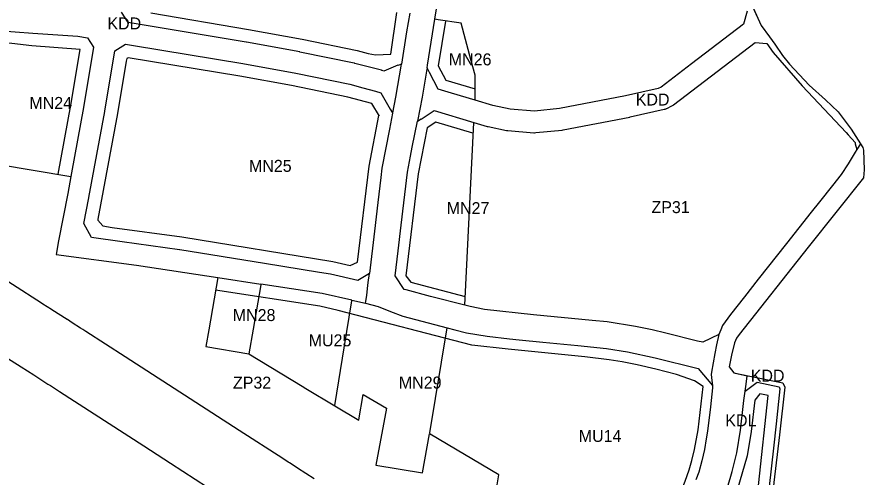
# Model space of a CAD drawing. Extents: x 7428103 to 7431580, y 5545880 to 5549002.
# Drawn here: x 7430729.6 to 7431122.6, y 5547228.4 to 5547441.7 of the extents above; entities that cross this region are included whole.
import ezdxf

# ---------------------------------------------------------------- set-up
doc = ezdxf.new("R2010")
doc.units = 0
for name, color, linetype in [('CZ_L_granica obszaru objętego planem', 7, 'Continuous'), ('CZ_L_linie rozgraniczające tereny o różnym przeznaczeniu oraz różnych warunkach ich zabudowy i zagospodarowania', 7, 'Continuous'), ('CZ_L_maksymalne nieprzekraczalne linie zabudowy', 7, 'Continuous'), ('CZ_L_opisy_linie rozgraniczające tereny o różnym przeznaczeniu oraz różnych warunkach ich zabudowy i zagospodarowania', 7, 'Continuous')]:
    doc.layers.add(name, color=color, linetype=linetype)

msp = doc.modelspace()

# ---------------------------------------------------------------- linework, layer by layer
at = {"layer": 'CZ_L_granica obszaru objętego planem'}
for p, q in [((7431066, 5547457.29), (7431074.9, 5547437.84)), ((7431074.9, 5547437.84), (7431078.67, 5547432.53)), ((7431078.67, 5547432.53), (7431081.21, 5547429.06)), ((7431081.21, 5547429.06), (7431084.68, 5547423.88)), ((7431084.68, 5547423.88), (7431087.93, 5547419.9)), ((7431087.93, 5547419.9), (7431097.2, 5547410.15)), ((7431097.2, 5547410.15), (7431104.64, 5547403.36)), ((7431104.64, 5547403.36), (7431110.55, 5547397.75)), ((7431110.55, 5547397.75), (7431116.54, 5547389.77)), ((7431116.54, 5547389.77), (7431121.98, 5547381.16)), ((7431121.98, 5547381.16), (7431122.33, 5547379.93)), ((7431122.33, 5547379.93), (7431122.59, 5547370.83)), ((7431122.59, 5547370.83), (7431122.26, 5547367.17)), ((7431122.26, 5547367.17), (7431096.66, 5547334.93)), ((7431096.66, 5547334.93), (7431064.69, 5547294.55)), ((7431063.46, 5547292.76), (7431062.41, 5547290.61)), ((7431064.69, 5547294.55), (7431063.46, 5547292.76)), ((7431062.41, 5547290.61), (7431061.1, 5547285)), ((7431061.1, 5547285), (7431060.06, 5547279.46)), ((7431060.06, 5547279.46), (7431062.23, 5547276.79)), ((7431062.23, 5547276.79), (7431069.54, 5547275.12)), ((7431069.54, 5547275.12), (7431084.96, 5547272.05)), ((7431084.96, 5547272.05), (7431085.82, 5547270.13)), ((7431085.82, 5547270.13), (7431083.35, 5547248.03)), ((7431083.35, 5547248.03), (7431080.69, 5547225.95))]:
    msp.add_line(p, q, dxfattribs=at)
at = {"layer": 'CZ_L_linie rozgraniczające tereny o różnym przeznaczeniu oraz różnych warunkach ich zabudowy i zagospodarowania'}
for p, q in [((7430923.49, 5547440.65), (7430924.59, 5547447.41)), ((7431068.4, 5547444.49), (7431066.66, 5547438.33)), ((7430781.17, 5547439.11), (7430778.02, 5547444.03)), ((7430911.79, 5547443.46), (7430910.38, 5547434.78)), ((7430920.03, 5547419.41), (7430923.49, 5547440.65)), ((7430924.97, 5547440.42), (7430923.49, 5547440.65)), ((7430924.97, 5547440.41), (7430924.97, 5547440.42)), ((7430935.73, 5547438.8), (7430924.97, 5547440.41)), ((7430836, 5547430.01), (7430781.17, 5547439.11)), ((7430940.35, 5547421.45), (7430935.73, 5547438.8)), ((7431066.66, 5547438.33), (7431042.5, 5547419.99)), ((7430710.81, 5547436.18), (7430736.98, 5547434.26)), ((7430736.98, 5547434.26), (7430757.87, 5547432.78)), ((7430757.87, 5547432.78), (7430757.89, 5547432.83)), ((7430757.89, 5547432.83), (7430762.29, 5547432.11)), ((7430910.38, 5547434.78), (7430907.96, 5547419.92)), ((7430762.29, 5547432.11), (7430765.15, 5547427.67)), ((7430775.03, 5547426.09), (7430779.88, 5547429.19)), ((7430779.88, 5547429.19), (7430783.72, 5547428.55)), ((7430783.72, 5547428.55), (7430834.32, 5547420.15)), ((7430836.08, 5547430), (7430836, 5547430.01)), ((7430860.75, 5547425.5), (7430836.08, 5547430)), ((7431048.55, 5547412.03), (7431072.07, 5547429.89)), ((7431072.07, 5547429.89), (7431077.54, 5547429.44)), ((7431077.54, 5547429.44), (7431080.47, 5547425.23)), ((7430765.15, 5547427.67), (7430760.49, 5547399.74)), ((7430770.35, 5547398.06), (7430775.03, 5547426.09)), ((7430860.87, 5547425.48), (7430860.75, 5547425.5)), ((7430886.1, 5547420.28), (7430860.87, 5547425.48)), ((7431080.47, 5547425.23), (7431093.8, 5547409.88)), ((7430942.1, 5547414.79), (7430940.35, 5547421.45)), ((7430834.32, 5547420.15), (7430858.91, 5547415.68)), ((7430886.19, 5547420.26), (7430886.1, 5547420.28)), ((7430886.35, 5547420.22), (7430886.19, 5547420.26)), ((7430898.66, 5547417.02), (7430886.35, 5547420.22)), ((7430898.81, 5547416.97), (7430898.66, 5547417.02)), ((7430899, 5547416.92), (7430898.81, 5547416.97)), ((7430899.87, 5547416.62), (7430899, 5547416.92)), ((7430906.36, 5547419.43), (7430899.87, 5547416.62)), ((7430905.35, 5547404.6), (7430907.96, 5547419.92)), ((7430907.96, 5547419.92), (7430906.34, 5547419.3)), ((7430906.34, 5547419.3), (7430906.36, 5547419.43)), ((7430919.84, 5547418.23), (7430919.58, 5547416.59)), ((7430919.84, 5547418.23), (7430920.03, 5547419.41)), ((7430921, 5547416), (7430919.84, 5547418.23)), ((7431042.48, 5547419.97), (7431028.49, 5547409.23)), ((7431042.5, 5547419.99), (7431042.48, 5547419.97)), ((7430858.91, 5547415.68), (7430883.95, 5547410.52)), ((7430919.58, 5547416.59), (7430917.59, 5547404.62)), ((7430925.02, 5547408.23), (7430921, 5547416.01)), ((7430921, 5547416.01), (7430921, 5547416)), ((7430942.16, 5547404.66), (7430942.1, 5547414.79)), ((7430883.95, 5547410.52), (7430890.06, 5547408.92)), ((7430890.06, 5547408.92), (7430895.97, 5547407.39)), ((7431028.49, 5547409.23), (7431027.13, 5547408.56)), ((7431034.19, 5547401), (7431048.55, 5547412.03)), ((7431093.8, 5547409.88), (7431093.92, 5547409.76)), ((7431093.92, 5547409.76), (7431093.93, 5547409.75)), ((7431093.93, 5547409.75), (7431114.3, 5547388.17)), ((7430895.97, 5547407.39), (7430898.35, 5547406.58)), ((7430898.35, 5547406.58), (7430902.73, 5547399.06)), ((7430931.16, 5547406.4), (7430925.02, 5547408.23)), ((7430942.09, 5547403.14), (7430931.16, 5547406.4)), ((7431011.91, 5547405.15), (7430981.34, 5547399.25)), ((7431027.13, 5547408.56), (7431011.91, 5547405.15)), ((7430903.92, 5547397.35), (7430905.35, 5547404.6)), ((7430917.59, 5547404.62), (7430915.36, 5547393.37)), ((7430942.09, 5547403.14), (7430942.16, 5547404.66)), ((7430950.39, 5547400.66), (7430942.09, 5547403.14)), ((7430760.49, 5547399.74), (7430754.89, 5547369.47)), ((7430762.95, 5547358.09), (7430770.33, 5547397.97)), ((7430770.33, 5547397.97), (7430770.35, 5547398.06)), ((7430902.73, 5547399.06), (7430902.73, 5547399.05)), ((7430902.73, 5547399.05), (7430903.76, 5547397.26)), ((7430903.76, 5547397.26), (7430903.92, 5547397.35)), ((7430903.76, 5547397.26), (7430903.87, 5547397.09)), ((7430917.1, 5547394.41), (7430923.2, 5547398.34)), ((7430923.2, 5547398.34), (7430941.58, 5547392.86)), ((7430958.42, 5547399), (7430950.39, 5547400.66)), ((7430969.75, 5547398.09), (7430958.42, 5547399)), ((7430981.34, 5547399.25), (7430969.75, 5547398.09)), ((7431014.03, 5547395.37), (7431029.9, 5547398.93)), ((7431029.9, 5547398.93), (7431030.3, 5547399.04)), ((7431030.3, 5547399.04), (7431030.61, 5547399.14)), ((7431030.61, 5547399.14), (7431030.91, 5547399.27)), ((7431030.91, 5547399.27), (7431031.02, 5547399.33)), ((7431031.02, 5547399.33), (7431033.36, 5547400.48)), ((7431033.36, 5547400.48), (7431033.99, 5547400.86)), ((7431033.99, 5547400.86), (7431034.09, 5547400.92)), ((7431034.09, 5547400.92), (7431034.15, 5547400.96)), ((7431034.15, 5547400.96), (7431034.19, 5547401)), ((7430903.87, 5547397.09), (7430902.4, 5547389.68)), ((7430912.98, 5547381.37), (7430915.36, 5547393.37)), ((7430915.36, 5547393.37), (7430917.11, 5547394.46)), ((7430917.11, 5547394.46), (7430917.1, 5547394.41)), ((7430983.01, 5547389.39), (7431013.88, 5547395.34)), ((7431013.88, 5547395.34), (7431014.03, 5547395.37)), ((7430902.4, 5547389.68), (7430898.87, 5547371.65)), ((7430937.37, 5547308.07), (7430941.58, 5547392.86)), ((7430941.58, 5547392.86), (7430947.74, 5547391.02)), ((7430947.74, 5547391.02), (7430947.75, 5547391.02)), ((7430947.75, 5547391.02), (7430948.07, 5547390.93)), ((7430948.07, 5547390.93), (7430948.15, 5547390.92)), ((7430948.15, 5547390.92), (7430956.7, 5547389.14)), ((7430970.3, 5547388.1), (7430982.56, 5547389.32)), ((7430982.56, 5547389.32), (7430983.01, 5547389.39)), ((7430956.7, 5547389.14), (7430957.31, 5547389.06)), ((7430957.31, 5547389.06), (7430969.4, 5547388.09)), ((7430969.4, 5547388.09), (7430969.68, 5547388.08)), ((7430969.68, 5547388.08), (7430970.3, 5547388.1)), ((7431114.3, 5547388.17), (7431115.24, 5547387.04)), ((7431115.24, 5547387.04), (7431118.39, 5547383.61)), ((7430912.15, 5547377.15), (7430912.98, 5547381.37)), ((7431118.39, 5547383.61), (7431118.48, 5547383.05)), ((7431118.48, 5547383.05), (7431118.51, 5547382.99)), ((7431118.51, 5547382.99), (7431118.51, 5547382.97)), ((7431118.51, 5547382.97), (7431119.24, 5547380.27)), ((7431120.88, 5547382.89), (7431119.24, 5547380.27)), ((7430695.95, 5547377.64), (7430754.58, 5547367.81)), ((7431118.48, 5547379.05), (7431115.17, 5547373.66)), ((7431119.24, 5547380.27), (7431118.48, 5547379.05)), ((7430910.73, 5547369.79), (7430912.15, 5547377.15)), ((7431115.17, 5547373.66), (7431112, 5547368.74)), ((7430898.87, 5547371.65), (7430898.35, 5547367.26)), ((7430907.81, 5547345.2), (7430910.73, 5547369.79)), ((7430754.58, 5547367.81), (7430753.12, 5547359.93)), ((7430754.89, 5547369.47), (7430754.58, 5547367.81)), ((7430898.35, 5547367.26), (7430896.97, 5547355.64)), ((7431112, 5547368.74), (7431107.92, 5547363.61)), ((7431107.92, 5547363.61), (7431101.87, 5547355.98)), ((7430753.12, 5547359.93), (7430748.93, 5547338.01)), ((7430760.56, 5547346.04), (7430762.9, 5547357.85)), ((7430762.9, 5547357.85), (7430762.91, 5547357.9)), ((7430762.91, 5547357.9), (7430762.95, 5547358.09)), ((7430896.97, 5547355.64), (7430895.39, 5547342.38)), ((7431101.87, 5547355.98), (7431098.13, 5547351.27)), ((7431098.13, 5547351.27), (7431086.59, 5547336.73)), ((7430764.19, 5547339.42), (7430760.56, 5547346.04)), ((7430895.39, 5547342.38), (7430893.07, 5547322.83)), ((7430906.4, 5547333.31), (7430907.81, 5547345.2)), ((7430778.4, 5547337.5), (7430764.19, 5547339.42)), ((7430748.93, 5547338.01), (7430747.83, 5547331.55)), ((7430805.07, 5547333.81), (7430778.4, 5547337.5)), ((7431086.59, 5547336.73), (7431073.52, 5547320.2)), ((7430747.83, 5547331.55), (7430785.06, 5547326.68)), ((7430805.13, 5547333.8), (7430805.07, 5547333.81)), ((7430805.19, 5547333.79), (7430805.13, 5547333.8)), ((7430844.47, 5547327.43), (7430805.19, 5547333.79)), ((7430905.03, 5547321.77), (7430906.4, 5547333.31)), ((7430738.77, 5547310.44), (7430711.71, 5547327.7)), ((7430785.06, 5547326.68), (7430822.71, 5547320.93)), ((7430869.92, 5547323.31), (7430844.47, 5547327.43)), ((7430875, 5547322.51), (7430869.92, 5547323.31)), ((7430887.67, 5547319.62), (7430875, 5547322.51)), ((7430893.07, 5547322.83), (7430887.67, 5547319.62)), ((7430892.58, 5547318.67), (7430893.07, 5547322.83)), ((7430822.71, 5547320.93), (7430818.59, 5547296.71)), ((7430822.71, 5547320.93), (7430842.79, 5547317.86)), ((7430892.24, 5547315.85), (7430892.58, 5547318.67)), ((7430909.3, 5547315.44), (7430905.03, 5547321.77)), ((7431073.52, 5547320.2), (7431067.09, 5547312.01)), ((7430842.74, 5547317.58), (7430839.1, 5547296.93)), ((7430842.76, 5547317.72), (7430842.74, 5547317.58)), ((7430842.79, 5547317.86), (7430842.76, 5547317.72)), ((7430871.14, 5547313.54), (7430842.79, 5547317.86)), ((7430891.85, 5547312.53), (7430892.24, 5547315.85)), ((7430910.08, 5547315.29), (7430909.3, 5547315.44)), ((7430921.52, 5547312.17), (7430910.08, 5547315.29)), ((7430884.97, 5547310.49), (7430871.14, 5547313.54)), ((7430891.29, 5547309.1), (7430891.85, 5547312.53)), ((7430937.37, 5547308.07), (7430921.52, 5547312.17)), ((7431067.09, 5547312.01), (7431060.57, 5547303.73)), ((7430741.38, 5547308.77), (7430738.77, 5547310.44)), ((7430741.65, 5547308.6), (7430741.38, 5547308.77)), ((7430745.68, 5547306.03), (7430741.65, 5547308.6)), ((7430881.41, 5547288.4), (7430884.92, 5547310.16)), ((7430884.92, 5547310.16), (7430884.96, 5547310.37)), ((7430884.96, 5547310.37), (7430884.97, 5547310.49)), ((7430884.97, 5547310.49), (7430891.29, 5547309.1)), ((7430891.29, 5547309.1), (7430897.15, 5547307.44)), ((7430897.15, 5547307.44), (7430897.16, 5547307.43)), ((7430897.16, 5547307.43), (7430902.87, 5547305.24)), ((7430939.86, 5547307.43), (7430937.37, 5547308.07)), ((7430946.45, 5547306.07), (7430939.86, 5547307.43)), ((7430745.7, 5547306.02), (7430745.68, 5547306.03)), ((7430745.7, 5547306.01), (7430745.7, 5547306.02)), ((7430752.93, 5547301.4), (7430745.7, 5547306.01)), ((7430902.87, 5547305.24), (7430908.54, 5547303.06)), ((7430908.54, 5547303.06), (7430929.17, 5547297.61)), ((7430969.26, 5547303.67), (7430946.45, 5547306.07)), ((7430996.45, 5547301.05), (7430969.26, 5547303.67)), ((7431060.57, 5547303.73), (7431056.97, 5547298.69)), ((7430752.96, 5547301.39), (7430752.93, 5547301.4)), ((7430752.93, 5547301.4), (7430752.93, 5547301.4)), ((7430755.27, 5547299.91), (7430752.96, 5547301.39)), ((7430759.13, 5547297.45), (7430755.27, 5547299.91)), ((7431003.38, 5547300.31), (7430996.45, 5547301.05)), ((7431016.54, 5547298.2), (7431003.38, 5547300.31)), ((7430705.22, 5547296.26), (7430731.53, 5547279.48)), ((7430760.12, 5547296.82), (7430759.13, 5547297.45)), ((7430760.15, 5547296.79), (7430760.12, 5547296.82)), ((7430760.19, 5547296.78), (7430760.15, 5547296.79)), ((7430761.53, 5547295.91), (7430760.19, 5547296.78)), ((7430779.78, 5547284.14), (7430761.53, 5547295.91)), ((7430818.59, 5547296.71), (7430817.23, 5547289.01)), ((7430839.1, 5547296.93), (7430837.11, 5547285.61)), ((7430921.12, 5547248.95), (7430929.17, 5547297.61)), ((7430929.17, 5547297.61), (7430932.66, 5547296.69)), ((7430932.66, 5547296.69), (7430938.18, 5547295.26)), ((7430938.18, 5547295.26), (7430947.66, 5547293.67)), ((7431024.3, 5547296.73), (7431016.54, 5547298.2)), ((7431030.55, 5547295.13), (7431024.3, 5547296.73)), ((7431045.28, 5547291.37), (7431030.55, 5547295.13)), ((7431056.08, 5547296.69), (7431055.22, 5547294.57)), ((7431056.97, 5547298.69), (7431056.08, 5547296.69)), ((7430947.66, 5547293.67), (7430958.06, 5547292.51)), ((7430958.06, 5547292.51), (7430962.6, 5547292.06)), ((7430962.6, 5547292.06), (7430973.61, 5547290.98)), ((7430973.61, 5547290.98), (7430989.81, 5547289.43)), ((7431047.74, 5547290.9), (7431045.28, 5547291.37)), ((7431055.22, 5547294.57), (7431047.74, 5547290.9)), ((7431055.22, 5547294.57), (7431054.13, 5547289.69)), ((7430817.23, 5547289.01), (7430837.09, 5547285.52)), ((7430877.23, 5547262.5), (7430881.41, 5547288.4)), ((7430989.81, 5547289.43), (7431003.05, 5547288.01)), ((7431003.05, 5547288.01), (7431012.89, 5547286.45)), ((7431054.13, 5547289.69), (7431053.34, 5547285.72)), ((7430832.65, 5547250.02), (7430779.78, 5547284.14)), ((7430837.11, 5547285.61), (7430837.09, 5547285.52)), ((7430837.09, 5547285.52), (7430861.88, 5547270.51)), ((7431012.89, 5547286.45), (7431025.65, 5547283.76)), ((7431025.65, 5547283.76), (7431045.59, 5547278.69)), ((7431053.34, 5547285.72), (7431051.86, 5547276.97)), ((7430731.53, 5547279.48), (7430737.4, 5547275.73)), ((7430737.4, 5547275.73), (7430743.95, 5547271.55)), ((7431045.59, 5547278.69), (7431052.23, 5547270.87)), ((7431051.7, 5547275.97), (7431051.69, 5547275.92)), ((7431051.69, 5547275.92), (7431051.98, 5547273.15)), ((7431051.86, 5547276.97), (7431051.7, 5547275.97)), ((7431067.84, 5547271.42), (7431068.35, 5547275.39)), ((7430743.95, 5547271.55), (7430745.1, 5547270.81)), ((7431051.98, 5547273.15), (7431052.23, 5547270.87)), ((7431067.43, 5547268.21), (7431073.04, 5547272.38)), ((7431067.43, 5547268.21), (7431067.84, 5547271.42)), ((7431073.04, 5547272.38), (7431083.28, 5547270.23)), ((7430745.1, 5547270.81), (7430749.39, 5547268.04)), ((7430749.39, 5547268.04), (7430788.46, 5547242.83)), ((7430861.88, 5547270.51), (7430863.55, 5547269.51)), ((7430863.55, 5547269.51), (7430877.05, 5547261.42)), ((7431052.35, 5547269.73), (7431051.41, 5547261.01)), ((7431052.23, 5547270.87), (7431052.35, 5547269.73)), ((7431066.89, 5547263.95), (7431067.43, 5547268.21)), ((7431083.49, 5547269.39), (7431081.75, 5547253.03)), ((7431083.28, 5547270.23), (7431083.49, 5547269.39)), ((7430888.2, 5547254.88), (7430890.21, 5547266.7)), ((7430890.21, 5547266.7), (7430900.97, 5547260.33)), ((7431066.56, 5547261.16), (7431066.89, 5547263.95)), ((7430877.05, 5547261.42), (7430877.11, 5547261.79)), ((7430877.05, 5547261.42), (7430888.18, 5547254.75)), ((7430877.11, 5547261.79), (7430877.23, 5547262.5)), ((7430900.97, 5547260.33), (7430896.09, 5547233.89)), ((7431051.41, 5547261.01), (7431050.02, 5547249.63)), ((7431065.24, 5547250.19), (7431066.56, 5547261.16)), ((7430888.18, 5547254.75), (7430888.2, 5547254.88)), ((7431081.75, 5547253.03), (7431080.54, 5547241.86)), ((7430852.86, 5547236.98), (7430832.65, 5547250.02)), ((7430917.69, 5547230.4), (7430920.95, 5547248.51)), ((7430920.95, 5547248.51), (7430921.36, 5547248.27)), ((7430921.36, 5547248.27), (7430921.12, 5547248.95)), ((7430953.18, 5547229.45), (7430921.36, 5547248.27)), ((7431050.02, 5547249.63), (7431049.4, 5547246.08)), ((7431063.58, 5547239.61), (7431065.24, 5547250.19)), ((7431049.4, 5547246.08), (7431048.51, 5547241.12)), ((7430788.46, 5547242.83), (7430800.88, 5547234.82)), ((7431048.51, 5547241.12), (7431047.32, 5547235.9)), ((7431080.54, 5547241.86), (7431078.52, 5547223.98)), ((7430855.34, 5547235.38), (7430852.86, 5547236.98)), ((7431061.38, 5547230.91), (7431063.58, 5547239.61)), ((7430800.88, 5547234.82), (7430823.75, 5547220.06)), ((7430856.04, 5547234.93), (7430855.34, 5547235.38)), ((7430859.58, 5547232.64), (7430856.04, 5547234.93)), ((7430859.68, 5547232.57), (7430859.58, 5547232.64)), ((7430867.45, 5547227.54), (7430859.68, 5547232.57)), ((7430896.09, 5547233.89), (7430917.69, 5547230.4)), ((7431047.32, 5547235.9), (7431045.9, 5547230.71)), ((7430944.87, 5547178.9), (7430953.17, 5547229.4)), ((7430953.17, 5547229.4), (7430953.21, 5547229.43)), ((7430953.21, 5547229.43), (7430953.18, 5547229.45)), ((7431045.9, 5547230.71), (7431044.58, 5547227.18)), ((7431059.1, 5547223.16), (7431060.78, 5547228.77)), ((7431060.78, 5547228.77), (7431061.38, 5547230.91))]:
    msp.add_line(p, q, dxfattribs=at)
for points in [[(7430986.2, 5547553.19), (7430987.53, 5547551.64), (7431001.23, 5547536.94), (7431016.1, 5547524.03), (7431031.6, 5547511.12), (7431032.93, 5547512.33), (7431040.53, 5547506.15), (7431048.48, 5547494.34), (7431057.8, 5547475.24), (7431066, 5547457.29), (7431074.9, 5547437.84), (7431078.67, 5547432.53), (7431081.21, 5547429.06), (7431084.68, 5547423.88), (7431087.93, 5547419.9), (7431097.2, 5547410.15), (7431104.64, 5547403.36), (7431110.55, 5547397.75), (7431116.54, 5547389.77), (7431120.88, 5547382.89)], [(7431120.88, 5547382.89), (7431121.98, 5547381.16), (7431122.33, 5547379.93), (7431122.59, 5547370.83), (7431122.26, 5547367.17), (7431096.66, 5547334.93), (7431064.69, 5547294.55), (7431063.46, 5547292.76), (7431062.41, 5547290.61), (7431061.1, 5547285), (7431060.06, 5547279.46), (7431062.23, 5547276.79), (7431068.35, 5547275.39)], [(7431068.35, 5547275.39), (7431069.54, 5547275.12), (7431084.96, 5547272.05), (7431085.82, 5547270.13), (7431083.35, 5547248.03), (7431080.69, 5547225.95), (7431079.79, 5547215.06), (7431081.67, 5547180.91), (7431083.32, 5547166.12), (7431084.84, 5547159.41), (7431087.12, 5547146.98), (7431087.38, 5547145.53), (7431098.88, 5547102.12), (7431104.84, 5547079.92)]]:
    msp.add_lwpolyline(points, dxfattribs=at)
at = {"layer": 'CZ_L_maksymalne nieprzekraczalne linie zabudowy'}
for points in [[(7430791.64, 5547443.59), (7430837.04, 5547435.92), (7430861.91, 5547431.39), (7430887.38, 5547426.14), (7430892.46, 5547424.84), (7430895.93, 5547424.14), (7430903, 5547424.51), (7430905.78, 5547443.88)], [(7430928.43, 5547439.85), (7430925.04, 5547419.06), (7430928.49, 5547412.41), (7430942.14, 5547408.42)], [(7430748.68, 5547368.9), (7430754.58, 5547400.78), (7430758.84, 5547426.64), (7430736.55, 5547428.28), (7430705.89, 5547431.93)], [(7430897.74, 5547395.69), (7430894.29, 5547401.62), (7430883.03, 5547404.56), (7430856.97, 5547409.93), (7430833.01, 5547414.29), (7430781.12, 5547422.86), (7430780.54, 5547422.49), (7430780.3, 5547421.23), (7430776.24, 5547396.92), (7430767.05, 5547347.96), (7430767.15, 5547347.54), (7430769.46, 5547344.9), (7430773.79, 5547344.18), (7430806.01, 5547339.74), (7430876.13, 5547328.4), (7430884.19, 5547326.56), (7430887.62, 5547328.1), (7430892.94, 5547372.55), (7430897.54, 5547396.03)], [(7430941.12, 5547387.88), (7430923.95, 5547392.89), (7430919.85, 5547390.3), (7430915.67, 5547369.01), (7430910.05, 5547321.66), (7430912.34, 5547318.72), (7430937.57, 5547312.07)], [(7431017.73, 5547189.85), (7431027.03, 5547202.56), (7431031.87, 5547209.94), (7431036.83, 5547219.63), (7431039.6, 5547226.5), (7431041.43, 5547231.76), (7431042.67, 5547236.07), (7431043.87, 5547241.19), (7431045.56, 5547250.24), (7431047.92, 5547270.34), (7431043.85, 5547273.01), (7431035.58, 5547275.9), (7431025.98, 5547278.42), (7431017.33, 5547280.38), (7431010.34, 5547281.76), (7431004.39, 5547282.73), (7430993.11, 5547284.13), (7430957.52, 5547287.64), (7430940.59, 5547289.59), (7430878.65, 5547305.59), (7430870.04, 5547307.64), (7430821.75, 5547315.01)], [(7431073.56, 5547224.54), (7431078.12, 5547266.21), (7431074.22, 5547267.02), (7431071.96, 5547264.01), (7431070.21, 5547249.59), (7431068.38, 5547238.22), (7431062.7, 5547218.6)]]:
    msp.add_lwpolyline(points, dxfattribs=at)

# ---------------------------------------------------------------- texts
at = {"layer": 'CZ_L_opisy_linie rozgraniczające tereny o różnym przeznaczeniu oraz różnych warunkach ich zabudowy i zagospodarowania'}
for s, p in [('KDD', (7430771.55, 5547435.96)), ('MN26', (7430929.93, 5547419.3)), ('KDD', (7431016.67, 5547400.68)), ('MN24', (7430735.35, 5547399.1)), ('MN25', (7430837.23, 5547369.93)), ('MN27', (7430928.96, 5547350.32)), ('ZP31', (7431023.96, 5547350.79)), ('MN28', (7430829.71, 5547300.75)), ('MU25', (7430864.94, 5547289.03)), ('KDD', (7431070.02, 5547272.64)), ('ZP32', (7430829.8, 5547269.41)), ('MN29', (7430906.76, 5547269.44)), ('KDL', (7431058.23, 5547251.9)), ('MU14', (7430990.24, 5547244.7))]:
    msp.add_text(s, height=5.549, dxfattribs=at).set_placement(p)

doc.saveas('drawing.dxf')
